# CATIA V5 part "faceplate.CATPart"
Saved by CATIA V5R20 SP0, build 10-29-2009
Part number: faceplate
Source: Unknown
Bounding box of the stored display mesh (mm): x -3.663 to 422.337, y 0 to 4, z 251.547 to 311.547
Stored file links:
  C:\Users\Ikarus\OneDrive - FH JOANNEUM\BAC - Arbeit 1\CAD Modell\CAD-Modell-Step files\Base\faceplate.CATPart
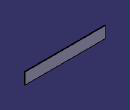
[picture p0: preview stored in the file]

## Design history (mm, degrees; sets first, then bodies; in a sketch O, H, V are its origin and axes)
Body1 (main body)
  Solid1 "Hauptkörper": solid without history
